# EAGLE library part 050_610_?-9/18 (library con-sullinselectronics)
.050 DIP EDGE CARD CONNECTOR .050 [1.27mm] CONTACT CENTERS .610" INSULATEOR HEIGHT Source: .050 DIP EDGE CARD.pdf
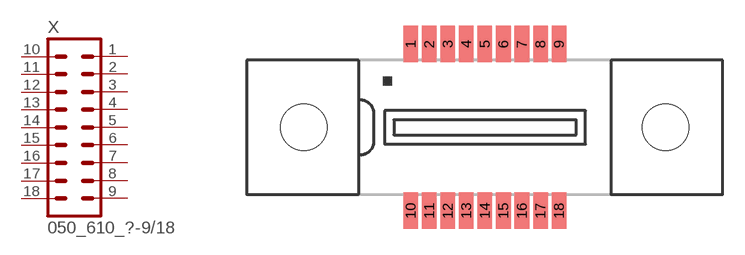
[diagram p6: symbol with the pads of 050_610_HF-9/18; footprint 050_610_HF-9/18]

Designator prefix X

## 050_610_HF-9/18 (OC_FARNELL: unknown; OC_NEWARK: unknown)  [050_610_HF-9/18]
1  1  pas
2  2  pas
3  3  pas
4  4  pas
5  5  pas
6  6  pas
7  7  pas
8  8  pas
9  9  pas
10  10  pas
11  11  pas
12  12  pas
13  13  pas
14  14  pas
15  15  pas
16  16  pas
17  17  pas
18  18  pas

## Footprint 050_610_HF-9/18 (pad centres in mm)
.050 DIP EDGE CARD CONNECTOR SURFACE MOUNT .050 [1.27mm] CONTACT CENTERS .610" INSULATEOR HEIGHT Source: .050 DIP EDGE CARD.pdf
smd 1 x 2.5: 1 -5.08,5.715; 2 -3.81,5.715; 3 -2.54,5.715; 4 -1.27,5.715; 5 0,5.715; 6 1.27,5.715; 7 2.54,5.715; 8 3.81,5.715; 9 5.08,5.715; 10 -5.08,-5.715; 11 -3.81,-5.715; 12 -2.54,-5.715; 13 -1.27,-5.715; 14 0,-5.715; 15 1.27,-5.715; 16 2.54,-5.715; 17 3.81,-5.715; 18 5.08,-5.715
hole 3.18 at -12.395,0
hole 3.18 at 12.395,0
